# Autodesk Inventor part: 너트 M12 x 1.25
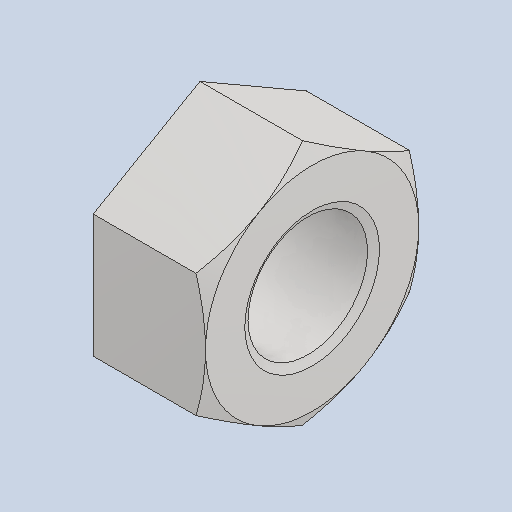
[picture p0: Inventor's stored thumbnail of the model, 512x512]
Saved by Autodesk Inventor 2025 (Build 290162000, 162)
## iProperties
Created: 2025-08
Part Number: 너트 M12 x 1.25
Material: 스테인리스강
Description: 6각 너트
Document SubType Name: Modeling
Designer: infra02
Density: 8.08 g/cm^3
Appearance: 기본값
Author: jhkim
Sending System: Autodesk Inventor 2026
Preprocessor: ST-DEVELOPER v20.1
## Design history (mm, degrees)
feature "Solid1"
node "솔리드1"
